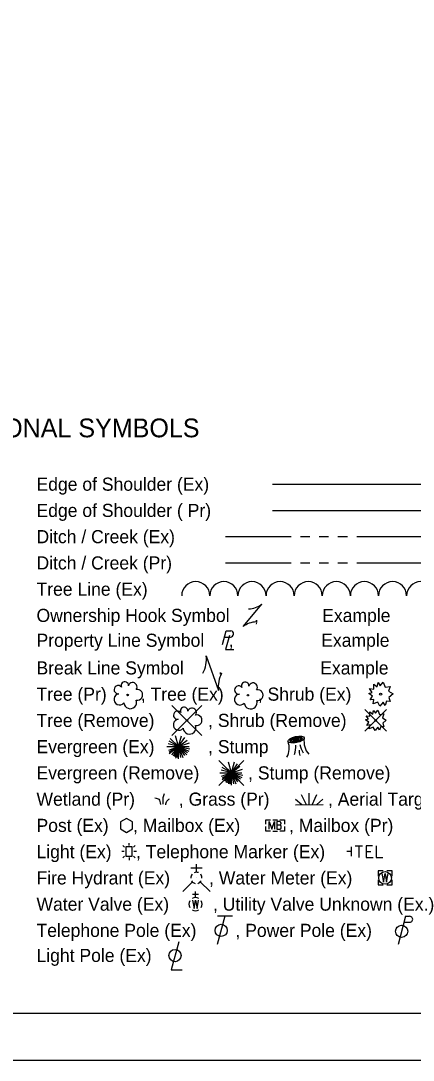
# Model space of a CAD drawing. Extents: x 0 to 34, y 0 to 22.
# Drawn here: x 8.13 to 12.32, y 0 to 11.09 of the extents above; entities that cross this region are included whole.
import ezdxf

# ---------------------------------------------------------------- set-up
doc = ezdxf.new("R2010")
doc.units = 0
for name, color, linetype in [('SH_Border', 7, 'Continuous'), ('SH_Cut_Line', 7, 'Continuous'), ('SH_Text', 7, 'Continuous')]:
    doc.layers.add(name, color=color, linetype=linetype)

msp = doc.modelspace()

# ---------------------------------------------------------------- linework, layer by layer
at = {"layer": 'SH_Border'}
msp.add_lwpolyline([(1.5, 21.5), (33.5, 21.5), (33.5, 0.5), (1.5, 0.5)], close=True, dxfattribs=at)
at = {"layer": 'SH_Cut_Line'}
msp.add_lwpolyline([(0, 0), (34, 0), (34, 22), (0, 22)], close=True, dxfattribs=at)
at = {"layer": 'SH_Text'}
for p, q in [((10.813, 6.145), (14.296, 6.145)), ((10.813, 5.865), (14.296, 5.865)), ((10.313, 5.585), (11.013, 5.585)), ((11.113, 5.585), (11.213, 5.585)), ((11.313, 5.585), (11.413, 5.585)), ((11.513, 5.585), (11.613, 5.585)), ((11.713, 5.585), (12.413, 5.585)), ((10.313, 5.305), (11.013, 5.305)), ((11.113, 5.305), (11.213, 5.305)), ((11.313, 5.305), (11.413, 5.305)), ((11.513, 5.305), (11.613, 5.305)), ((11.713, 5.305), (12.413, 5.305)), ((10.5, 4.625), (10.7, 4.865)), ((10.6, 4.745), (10.6, 4.745)), ((10.3, 4.514), (10.365, 4.514)), ((10.34, 4.483), (10.34, 4.483)), ((10.107, 4.313), (10.237, 3.945)), ((10.172, 4.129), (10.172, 4.129)), ((9.74, 3.785), (10.061, 3.464)), ((10.061, 3.785), (9.74, 3.464)), ((11.799, 3.741), (12.031, 3.509)), ((12.031, 3.741), (11.799, 3.509)), ((9.901, 3.625), (9.901, 3.625)), ((11.915, 3.625), (11.915, 3.625)), ((9.811, 3.345), (9.78, 3.46)), ((9.811, 3.345), (9.843, 3.462)), ((9.811, 3.345), (9.877, 3.442)), ((9.688, 3.345), (9.811, 3.345)), ((9.811, 3.345), (9.701, 3.374)), ((9.811, 3.345), (9.704, 3.305)), ((9.811, 3.345), (9.712, 3.287)), ((9.811, 3.345), (9.713, 3.402)), ((9.811, 3.345), (9.713, 3.27)), ((9.811, 3.345), (9.724, 3.432)), ((9.811, 3.345), (9.737, 3.258)), ((9.811, 3.345), (9.753, 3.244)), ((9.811, 3.345), (9.769, 3.236)), ((9.811, 3.345), (9.78, 3.223)), ((9.811, 3.345), (9.798, 3.23)), ((9.811, 3.345), (9.903, 3.415)), ((9.811, 3.345), (9.93, 3.385)), ((9.811, 3.345), (9.924, 3.347)), ((9.811, 3.214), (9.811, 3.345)), ((9.811, 3.345), (9.834, 3.229)), ((9.811, 3.345), (9.859, 3.228)), ((9.811, 3.345), (9.875, 3.25)), ((9.811, 3.345), (9.901, 3.256)), ((9.811, 3.345), (9.907, 3.281)), ((9.811, 3.345), (9.923, 3.296)), ((9.811, 3.345), (9.932, 3.321)), ((11.085, 3.345), (11.085, 3.345)), ((10.242, 3.198), (10.509, 2.931)), ((10.509, 3.198), (10.242, 2.931)), ((10.375, 3.065), (10.277, 3.122)), ((10.375, 3.065), (10.288, 3.152)), ((10.375, 3.065), (10.344, 3.18)), ((10.375, 3.065), (10.407, 3.182)), ((10.375, 3.065), (10.442, 3.162)), ((10.375, 3.065), (10.467, 3.135)), ((10.375, 3.065), (10.494, 3.105)), ((10.252, 3.065), (10.375, 3.065)), ((10.375, 3.065), (10.265, 3.094)), ((10.375, 3.065), (10.268, 3.026)), ((10.375, 3.065), (10.276, 3.008)), ((10.375, 3.065), (10.277, 2.99)), ((10.375, 3.065), (10.302, 2.978)), ((10.375, 3.065), (10.317, 2.964)), ((10.375, 3.065), (10.334, 2.956)), ((10.375, 3.065), (10.344, 2.943)), ((10.375, 3.065), (10.362, 2.95)), ((10.375, 3.065), (10.488, 3.067)), ((10.375, 2.934), (10.375, 3.065)), ((10.375, 3.065), (10.398, 2.949)), ((10.375, 3.065), (10.423, 2.948)), ((10.375, 3.065), (10.439, 2.97)), ((10.375, 3.065), (10.465, 2.977)), ((10.375, 3.065), (10.471, 3.001)), ((10.375, 3.065), (10.487, 3.016)), ((10.375, 3.065), (10.496, 3.041)), ((10.375, 3.065), (10.375, 3.065)), ((11.128, 2.724), (11.06, 2.781)), ((11.177, 2.724), (11.125, 2.83)), ((11.207, 2.725), (11.205, 2.85)), ((11.237, 2.725), (11.286, 2.833)), ((11.285, 2.726), (11.352, 2.785)), ((11.061, 2.723), (11.353, 2.727)), ((10.818, 2.566), (10.868, 2.566)), ((10.818, 2.444), (10.868, 2.444)), ((10.843, 2.505), (10.843, 2.505)), ((9.232, 2.225), (9.205, 2.225)), ((9.236, 2.273), (9.217, 2.292)), ((9.284, 2.289), (9.284, 2.315)), ((9.284, 2.225), (9.284, 2.225)), ((9.35, 2.292), (9.332, 2.273)), ((9.363, 2.225), (9.336, 2.225)), ((11.656, 2.225), (11.607, 2.225)), ((11.656, 2.175), (11.656, 2.275)), ((9.236, 2.176), (9.217, 2.158)), ((9.284, 2.161), (9.284, 2.134)), ((9.35, 2.158), (9.332, 2.176)), ((10.062, 2.048), (9.942, 2.048)), ((10.002, 2.005), (10.002, 2.091)), ((9.96, 1.902), (9.856, 1.798)), ((10.002, 1.945), (10.002, 1.945)), ((10.002, 1.945), (10.002, 1.945)), ((10.044, 1.902), (10.148, 1.798)), ((12.015, 1.945), (12.015, 1.945)), ((9.993, 1.735), (9.993, 1.798)), ((10.025, 1.767), (9.961, 1.767)), ((9.993, 1.665), (9.993, 1.665)), ((10.306, 1.535), (10.225, 1.235)), ((10.386, 1.535), (10.226, 1.535)), ((12.235, 1.535), (12.154, 1.235)), ((12.218, 1.471), (12.277, 1.471)), ((12.235, 1.535), (12.277, 1.535))]:
    msp.add_line(p, q, dxfattribs=at)
for points in [[(10.279, 4.434), (10.318, 4.582), (10.37, 4.582)], [(10.354, 4.531), (10.314, 4.383), (10.401, 4.383)], [(11.964, 3.995), (11.994, 4.032), (12.015, 3.979), (12.07, 3.988), (12.053, 3.938), (12.1, 3.908), (12.057, 3.871), (12.07, 3.826), (12.032, 3.829), (12.016, 3.783), (11.994, 3.818), (11.96, 3.777), (11.939, 3.821), (11.888, 3.8), (11.897, 3.847), (11.857, 3.843), (11.881, 3.882), (11.842, 3.911), (11.879, 3.924), (11.849, 3.964), (11.895, 3.959), (11.894, 4.011), (11.931, 3.982), (11.942, 4.031), (11.964, 3.995)], [(11.912, 3.702), (11.937, 3.733), (11.955, 3.688), (12.001, 3.696), (11.987, 3.653), (12.027, 3.628), (11.991, 3.596), (12.001, 3.557), (11.969, 3.56), (11.956, 3.522), (11.937, 3.551), (11.909, 3.516), (11.89, 3.554), (11.847, 3.536), (11.855, 3.576), (11.821, 3.572), (11.841, 3.606), (11.808, 3.63), (11.839, 3.641), (11.814, 3.675), (11.853, 3.671), (11.852, 3.715), (11.884, 3.69), (11.893, 3.732), (11.912, 3.702)], [(9.191, 2.467), (9.256, 2.43), (9.32, 2.467), (9.32, 2.542), (9.256, 2.58), (9.191, 2.542), (9.191, 2.467)], [(10.743, 2.517), (10.743, 2.566), (10.792, 2.566)], [(10.894, 2.566), (10.943, 2.566), (10.943, 2.517)], [(10.792, 2.444), (10.743, 2.444), (10.743, 2.492)], [(10.779, 2.465), (10.779, 2.545), (10.808, 2.465), (10.835, 2.545), (10.835, 2.465)], [(10.895, 2.508), (10.898, 2.511), (10.9, 2.513), (10.901, 2.515), (10.901, 2.516), (10.903, 2.519), (10.903, 2.521), (10.905, 2.525), (10.905, 2.527), (10.905, 2.53), (10.904, 2.533), (10.903, 2.537), (10.901, 2.539), (10.898, 2.542), (10.895, 2.543), (10.894, 2.543), (10.891, 2.545), (10.86, 2.545), (10.86, 2.465), (10.895, 2.465), (10.899, 2.467), (10.903, 2.47), (10.906, 2.475), (10.908, 2.481), (10.908, 2.487), (10.908, 2.491), (10.907, 2.494), (10.905, 2.5), (10.901, 2.504), (10.895, 2.508), (10.86, 2.508)], [(10.943, 2.492), (10.943, 2.444), (10.894, 2.444)], [(11.697, 2.287), (11.775, 2.287)], [(11.737, 2.287), (11.737, 2.162)], [(11.882, 2.287), (11.814, 2.287), (11.814, 2.162), (11.887, 2.162)], [(11.814, 2.225), (11.863, 2.225)], [(11.922, 2.287), (11.922, 2.162), (11.99, 2.162)], [(11.995, 2.02), (11.94, 2.02), (11.94, 1.965)], [(12.09, 1.965), (12.09, 2.02), (12.035, 2.02)], [(11.94, 1.925), (11.94, 1.87), (11.995, 1.87)], [(11.982, 1.99), (11.999, 1.9), (12.015, 1.99), (12.032, 1.9), (12.049, 1.99)], [(12.035, 1.87), (12.09, 1.87), (12.09, 1.925)], [(9.961, 1.706), (9.977, 1.62), (9.993, 1.706), (10.009, 1.62), (10.025, 1.706)], [(9.813, 1.263), (9.734, 0.964), (9.852, 0.964)]]:
    msp.add_lwpolyline(points, dxfattribs=at)
msp.add_lwpolyline([(9.25, 2.175), (9.317, 2.175), (9.317, 2.275), (9.25, 2.275)], close=True, dxfattribs=at)
for centre, radius in [((9.268, 3.897), 0.0084), ((10.552, 3.893), 0.0072), ((11.968, 3.905), 0.0115), ((9.901, 3.625), 0.0072), ((11.915, 3.625), 0.00979), ((12.015, 1.945), 0.0675), ((10.266, 1.385), 0.065), ((12.192, 1.375), 0.065), ((9.774, 1.116), 0.065)]:
    msp.add_circle(centre, radius, dxfattribs=at)
for centre, radius, start, end in [((9.995, 4.955), 0.15, 0.0098, 179.9926), ((10.295, 4.955), 0.15, 0.0098, 179.9926), ((10.595, 4.955), 0.15, 0.0098, 179.9926), ((10.895, 4.955), 0.15, 0.0098, 179.9926), ((11.195, 4.955), 0.15, 0.0098, 179.9926), ((11.495, 4.955), 0.15, 0.0098, 179.9926), ((11.795, 4.955), 0.15, 0.0098, 179.9926), ((12.095, 4.955), 0.15, 0.0098, 179.9926), ((12.395, 4.955), 0.15, 0.0098, 179.9926), ((10.542, 5.08), 0.267, 273.6945, 306.337), ((10.658, 4.41), 0.267, 93.6945, 126.337), ((10.365, 4.548), 0.0345, 270.471, 81.3281), ((9.775, 4.281), 0.334, 332.9422, 5.5848), ((10.569, 3.978), 0.334, 152.9422, 185.5848), ((9.168, 3.953), 0.0441, 39.0625, 279.5412), ((9.238, 3.998), 0.0395, 354.0047, 205.9741), ((9.322, 3.982), 0.0466, 323.83, 165.0376), ((10.453, 3.949), 0.0441, 39.0625, 279.5412), ((10.523, 3.994), 0.0395, 354.0047, 205.9741), ((10.607, 3.978), 0.0466, 323.83, 165.0376), ((9.182, 3.85), 0.0592, 96.1722, 320.5737), ((9.371, 3.898), 0.0574, 259.1453, 101.4596), ((10.467, 3.847), 0.0592, 96.1722, 320.5737), ((10.656, 3.894), 0.0574, 259.1453, 101.4596), ((9.296, 3.818), 0.0685, 184.9476, 19.4572), ((10.581, 3.815), 0.0685, 184.9476, 19.4572), ((9.801, 3.681), 0.0441, 39.0625, 279.5412), ((9.871, 3.726), 0.0395, 354.0047, 205.9741), ((9.955, 3.71), 0.0466, 323.83, 165.0376), ((10.004, 3.626), 0.0574, 259.1453, 101.4596), ((9.815, 3.578), 0.0592, 96.1722, 320.5737), ((9.929, 3.547), 0.0685, 184.9476, 19.4572), ((10.793, 3.327), 0.2, 331.5338, 20.9269), ((10.809, 3.346), 0.253, 340.7938, 3.5481), ((11.41, 3.448), 0.316, 194.9653, 212.1216), ((11.365, 3.402), 0.215, 171.4106, 219.9194), ((11.28, 3.305), 0.182, 178.7926, 197.1224), ((10.002, 1.945), 0.06, 68.1395, 112.038), ((10.002, 1.945), 0.06, 140.021, 184.0629), ((10.002, 1.945), 0.06, 211.8788, 255.8479), ((10.002, 1.945), 0.06, 283.8239, 329.9097), ((10.002, 1.945), 0.06, 356.0165, 39.9889), ((9.993, 1.665), 0.07, 150.0184, 209.9816), ((9.993, 1.665), 0.07, 60.0184, 120.0157), ((9.993, 1.665), 0.07, 330.0184, 29.9816), ((9.993, 1.665), 0.07, 239.9843, 299.9816), ((12.278, 1.503), 0.0319, 268.8767, 91.1233)]:
    msp.add_arc(centre, radius, start, end, dxfattribs=at)
for major_axis in [(0.0868, 0.0187), (0.0651, 0.0141), (0.0488, 0.0105), (0.0275, 0.0059), (0.0154, 0.0033)]:
    msp.add_ellipse((11.066, 3.42), major_axis=major_axis, ratio=0.36865, dxfattribs=at)
for points in [[(9.56, 2.8), (9.601, 2.783), (9.619, 2.729)], [(9.647, 2.733), (9.647, 2.781), (9.653, 2.825), (9.662, 2.846)], [(9.675, 2.726), (9.687, 2.765), (9.716, 2.788)]]:
    msp.add_spline(points, degree=3, dxfattribs=at)

# ---------------------------------------------------------------- texts
for s, height, p in [('CONVENTIONAL SYMBOLS', 0.2, (6.558, 6.645)), ('Edge of Shoulder (Ex)', 0.14, (8.296, 6.075)), ('Edge of Shoulder ( Pr)', 0.14, (8.296, 5.795)), ('Ditch / Creek (Ex)', 0.14, (8.296, 5.515)), ('Ditch / Creek (Pr)', 0.14, (8.296, 5.235)), ('Tree Line (Ex)', 0.14, (8.296, 4.955)), ('Ownership Hook Symbol     ,             Example', 0.14, (8.296, 4.675)), ('Property Line Symbol     ,                  Example', 0.14, (8.296, 4.41)), ('Break Line Symbol       ,                    Example', 0.14, (8.296, 4.115)), ('Tree (Pr)       , Tree (Ex)       , Shrub (Ex)', 0.14, (8.296, 3.835)), ('Tree (Remove)           , Shrub (Remove)', 0.14, (8.296, 3.555)), ('Evergreen (Ex)           , Stump ', 0.14, (8.296, 3.275)), ('Evergreen (Remove)          , Stump (Remove)', 0.14, (8.296, 2.995)), ('Wetland (Pr)         , Grass (Pr)            , Aerial Target    ', 0.14, (8.296, 2.715)), ('Post (Ex)     , Mailbox (Ex)          , Mailbox (Pr)', 0.14, (8.296, 2.435)), ('Light (Ex)     , Telephone Marker (Ex)     ', 0.14, (8.296, 2.155)), ('Fire Hydrant (Ex)        , Water Meter (Ex)', 0.14, (8.296, 1.875)), ('Water Valve (Ex)         , Utility Valve Unknown (Ex.)', 0.14, (8.296, 1.595)), ('Telephone Pole (Ex)        , Power Pole (Ex)', 0.14, (8.296, 1.315)), ('Light Pole (Ex)     ', 0.14, (8.296, 1.048))]:
    msp.add_text(s, height=height, dxfattribs=at).set_placement(p)

doc.saveas('drawing.dxf')
